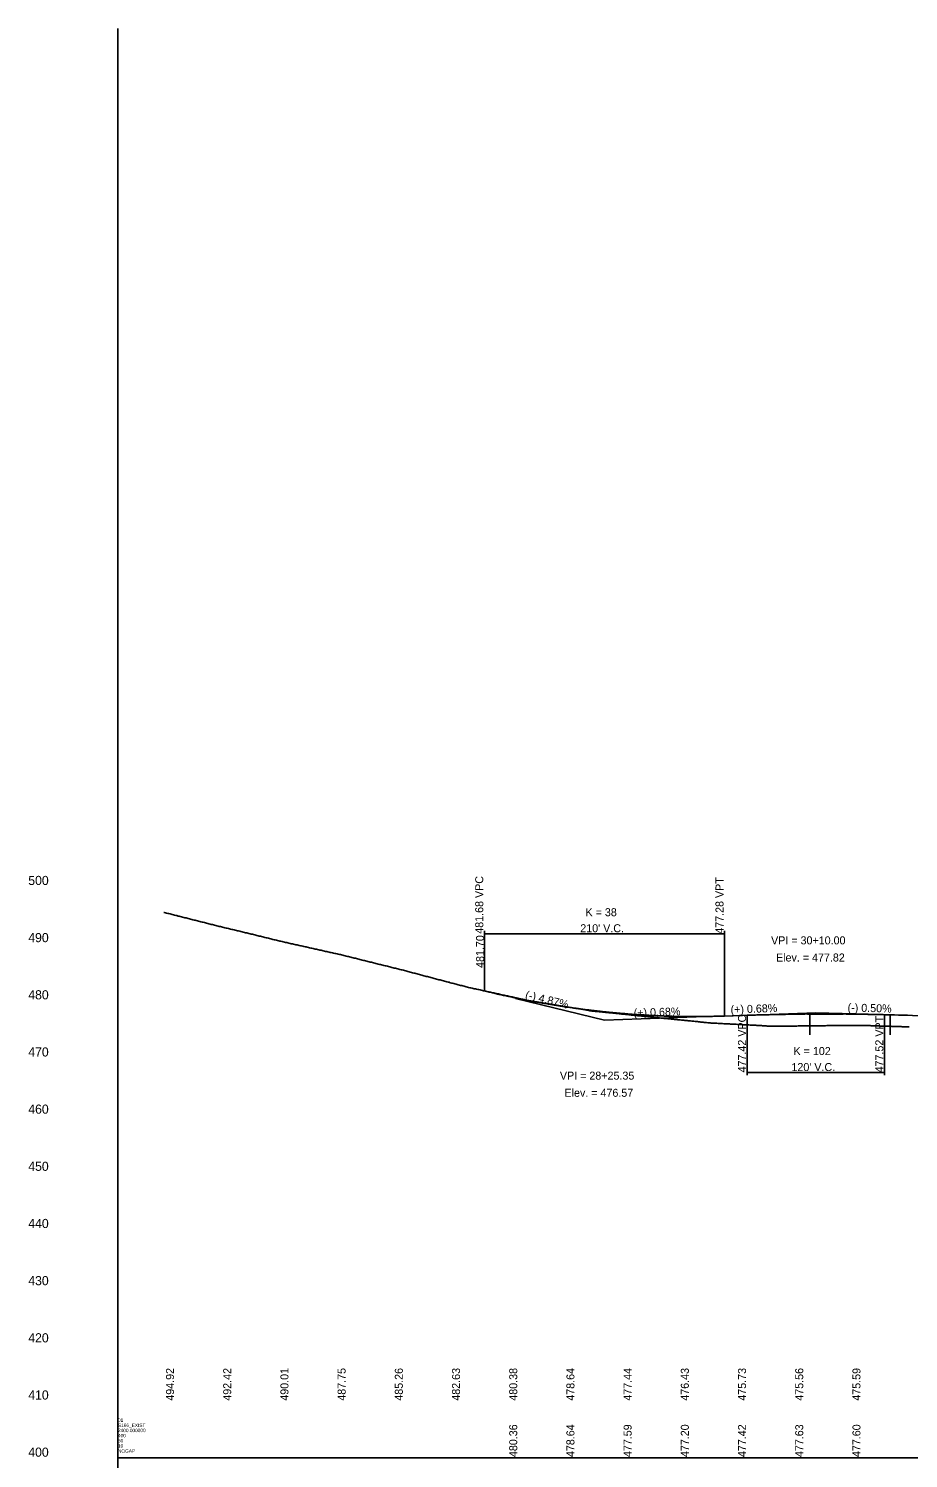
# Model space of a CAD drawing. Extents: x 1690070 to 1696783, y 823417 to 829859.
# Drawn here: x 1695305 to 1696074, y 824666 to 825917 of the extents above; entities that cross this region are included whole.
import ezdxf

# ---------------------------------------------------------------- set-up
doc = ezdxf.new("R2010")
doc.units = 0
for name, color, linetype in [('RD_DDB_ElevTX', 7, 'Continuous'), ('RD_DDB_GradeTX', 7, 'Continuous'), ('RD_DDB_Profile_EX', 7, 'Continuous'), ('RD_DDB_Profile_Lbl', 7, 'Continuous'), ('RD_DDB_Profile_PR', 7, 'Continuous'), ('RD_DDB_StripGrade', 7, 'Continuous'), ('RD_DDB_VCLbl', 7, 'Continuous'), ('RD_GPK_Profile_Cell', 7, 'Continuous'), ('RD_PD_Bridge', 7, 'Continuous')]:
    doc.layers.add(name, color=color, linetype=linetype)

msp = doc.modelspace()

# ---------------------------------------------------------------- linework, layer by layer
at = {"layer": 'RD_DDB_GradeTX'}
for p, q in [((1695730.6, 825068.6), (1695808.3, 825049.6)), ((1695913, 825053.2), (1695993, 825055.9)), ((1696073, 825053.9), (1695993, 825055.9)), ((1695888.3, 825052.4), (1695808.3, 825049.6))]:
    msp.add_line(p, q, dxfattribs=at)
at = {"layer": 'RD_DDB_Profile_EX'}
for points in [[(1695423, 825143.9), (1695423.5, 825143.8), (1695424.5, 825143.5), (1695425.5, 825143.3), (1695426.5, 825143), (1695427.5, 825142.8), (1695428.5, 825142.5), (1695429.5, 825142.2), (1695430.5, 825142), (1695431.5, 825141.7), (1695432.5, 825141.5), (1695433.5, 825141.2), (1695434.5, 825141), (1695435.5, 825140.7), (1695436.5, 825140.5), (1695437.5, 825140.2), (1695438.5, 825140), (1695439.5, 825139.7), (1695440.5, 825139.5), (1695441.5, 825139.2), (1695442.5, 825139), (1695443.5, 825138.7), (1695444.5, 825138.5), (1695445.5, 825138.2), (1695446.5, 825138), (1695447.5, 825137.7), (1695448.5, 825137.5), (1695449.5, 825137.2), (1695450.5, 825137), (1695451.5, 825136.7), (1695452.5, 825136.5), (1695453.5, 825136.2), (1695454.5, 825135.9), (1695455.5, 825135.7), (1695456.5, 825135.4), (1695457.5, 825135.2), (1695458.5, 825134.9), (1695459.5, 825134.7), (1695460.5, 825134.4), (1695461.5, 825134.2), (1695462.5, 825133.9), (1695463.5, 825133.7), (1695464.5, 825133.4), (1695465.5, 825133.2), (1695466.5, 825132.9), (1695467.5, 825132.7), (1695468.5, 825132.4), (1695469.5, 825132.1), (1695470.5, 825131.9), (1695471.5, 825131.6), (1695472.5, 825131.4), (1695473.5, 825131.2), (1695474.5, 825130.9), (1695475.5, 825130.7), (1695476.5, 825130.4), (1695477.5, 825130.2), (1695478.5, 825130), (1695479.5, 825129.7), (1695480.5, 825129.5), (1695481.5, 825129.2), (1695482.5, 825129), (1695483.5, 825128.8), (1695484.5, 825128.5), (1695485.5, 825128.3), (1695486.5, 825128), (1695487.5, 825127.8), (1695488.5, 825127.6), (1695489.5, 825127.3), (1695490.5, 825127.1), (1695491.5, 825126.8), (1695492.5, 825126.6), (1695493.5, 825126.3), (1695494.5, 825126.1), (1695495.5, 825125.9), (1695496.5, 825125.6), (1695497.5, 825125.4), (1695498.5, 825125.1), (1695499.5, 825124.9), (1695500.5, 825124.7), (1695501.5, 825124.4), (1695502.5, 825124.2), (1695503.5, 825123.9), (1695504.5, 825123.7), (1695505.5, 825123.4), (1695506.5, 825123.2), (1695507.5, 825123), (1695508.5, 825122.7), (1695509.5, 825122.5), (1695510.5, 825122.2), (1695511.5, 825122), (1695512.5, 825121.7), (1695513.5, 825121.5), (1695514.5, 825121.3), (1695515.5, 825121), (1695516.5, 825120.8), (1695517.5, 825120.5), (1695518.5, 825120.3), (1695519.5, 825120), (1695520.5, 825119.8), (1695521.5, 825119.6), (1695522.5, 825119.3)], [(1695522.5, 825119.3), (1695523.5, 825119.1), (1695524.5, 825118.8), (1695525.5, 825118.6), (1695526.5, 825118.3), (1695527.5, 825118.1), (1695528.5, 825117.8), (1695529.5, 825117.6), (1695530.5, 825117.4), (1695531.5, 825117.2), (1695532.5, 825117), (1695533.5, 825116.7), (1695534.5, 825116.5), (1695535.5, 825116.3), (1695536.5, 825116.1), (1695537.5, 825115.8), (1695538.5, 825115.6), (1695539.5, 825115.4), (1695540.5, 825115.2), (1695541.5, 825114.9), (1695542.5, 825114.7), (1695543.5, 825114.5), (1695544.5, 825114.3), (1695545.5, 825114), (1695546.5, 825113.8), (1695547.5, 825113.6), (1695548.5, 825113.4), (1695549.5, 825113.1), (1695550.5, 825112.9), (1695551.5, 825112.7), (1695552.5, 825112.5), (1695553.5, 825112.2), (1695554.5, 825112), (1695555.5, 825111.8), (1695556.5, 825111.6), (1695557.5, 825111.3), (1695558.5, 825111.1), (1695559.5, 825110.9), (1695560.5, 825110.7), (1695561.5, 825110.5), (1695562.5, 825110.2), (1695563.5, 825110), (1695564.5, 825109.8), (1695565.5, 825109.6), (1695566.5, 825109.3), (1695567.5, 825109.1), (1695568.5, 825108.9), (1695569.5, 825108.7), (1695570.5, 825108.4), (1695571.5, 825108.2), (1695572.5, 825108), (1695573.5, 825107.8), (1695574.5, 825107.5), (1695575.5, 825107.3), (1695576.5, 825107.1), (1695577.5, 825106.9), (1695578.5, 825106.6), (1695579.5, 825106.4), (1695580.5, 825106.2), (1695581.5, 825105.9), (1695582.5, 825105.6), (1695583.5, 825105.4), (1695584.5, 825105.2), (1695585.5, 825104.9), (1695586.5, 825104.7), (1695587.5, 825104.4), (1695588.5, 825104.2), (1695589.5, 825103.9), (1695590.5, 825103.7), (1695591.5, 825103.4), (1695592.5, 825103.2), (1695593.5, 825102.9), (1695594.5, 825102.7), (1695595.5, 825102.4), (1695596.5, 825102.2), (1695597.5, 825101.9), (1695598.5, 825101.7), (1695599.5, 825101.4), (1695600.5, 825101.2), (1695601.5, 825100.9), (1695602.5, 825100.7), (1695603.5, 825100.4), (1695604.5, 825100.2), (1695605.5, 825099.9), (1695606.5, 825099.7), (1695607.5, 825099.4), (1695608.5, 825099.2), (1695609.5, 825098.9), (1695610.5, 825098.7), (1695611.5, 825098.4), (1695612.5, 825098.2), (1695613.5, 825097.9), (1695614.5, 825097.7), (1695615.5, 825097.5), (1695616.5, 825097.2), (1695617.5, 825097), (1695618.5, 825096.7), (1695619.5, 825096.5), (1695620.5, 825096.2), (1695621.5, 825096), (1695622.5, 825095.7)], [(1695622.5, 825095.7), (1695623.5, 825095.5), (1695624.5, 825095.2), (1695625.5, 825095), (1695626.5, 825094.7), (1695627.5, 825094.5), (1695628.5, 825094.2), (1695629.5, 825094), (1695630.5, 825093.7), (1695631.5, 825093.5), (1695632.5, 825093.2), (1695633.5, 825093), (1695634.5, 825092.7), (1695635.5, 825092.4), (1695636.5, 825092.2), (1695637.5, 825091.9), (1695638.5, 825091.6), (1695639.5, 825091.4), (1695640.5, 825091.1), (1695641.5, 825090.8), (1695642.5, 825090.6), (1695643.5, 825090.3), (1695644.5, 825090.1), (1695645.5, 825089.8), (1695646.5, 825089.5), (1695647.5, 825089.3), (1695648.5, 825089), (1695649.5, 825088.7), (1695650.5, 825088.5), (1695651.5, 825088.2), (1695652.5, 825087.9), (1695653.5, 825087.7), (1695654.5, 825087.4), (1695655.5, 825087.2), (1695656.5, 825086.9), (1695657.5, 825086.6), (1695658.5, 825086.4), (1695659.5, 825086.1), (1695660.5, 825085.8), (1695661.5, 825085.6), (1695662.5, 825085.3), (1695663.5, 825085), (1695664.5, 825084.8), (1695665.5, 825084.5), (1695666.5, 825084.3), (1695667.5, 825084), (1695668.5, 825083.7), (1695669.5, 825083.5), (1695670.5, 825083.2), (1695671.5, 825082.9), (1695672.5, 825082.7), (1695673.5, 825082.4), (1695674.5, 825082.1), (1695675.5, 825081.9), (1695676.5, 825081.6), (1695677.5, 825081.4), (1695678.5, 825081.1), (1695679.5, 825080.8), (1695680.5, 825080.6), (1695681.5, 825080.3), (1695682.5, 825080), (1695683.5, 825079.8), (1695684.5, 825079.5), (1695685.5, 825079.2), (1695686.5, 825079), (1695687.5, 825078.7), (1695688.5, 825078.5), (1695689.5, 825078.2), (1695690.5, 825078), (1695691.5, 825077.8), (1695692.5, 825077.6), (1695693.5, 825077.4), (1695694.5, 825077.1), (1695695.5, 825076.9), (1695696.5, 825076.7), (1695697.5, 825076.5), (1695698.5, 825076.3), (1695699.5, 825076), (1695700.5, 825075.8), (1695701.5, 825075.6), (1695702.5, 825075.4), (1695703.5, 825075.2), (1695704.5, 825074.9), (1695705.5, 825074.7), (1695706.5, 825074.5), (1695707.5, 825074.3), (1695708.5, 825074.1), (1695709.5, 825073.8), (1695710.5, 825073.6), (1695711.5, 825073.4), (1695712.5, 825073.2), (1695713.5, 825073), (1695714.5, 825072.7), (1695715.5, 825072.5), (1695716.5, 825072.3), (1695717.5, 825072.1), (1695718.5, 825071.9), (1695719.5, 825071.6), (1695720.5, 825071.4), (1695721.5, 825071.2), (1695722.5, 825071)], [(1695722.5, 825071), (1695723.5, 825070.8), (1695724.5, 825070.5), (1695725.5, 825070.3), (1695726.5, 825070.1), (1695727.5, 825069.9), (1695728.5, 825069.7), (1695729.5, 825069.4), (1695730.5, 825069.2), (1695731.5, 825069), (1695732.5, 825068.8), (1695733.5, 825068.6), (1695734.5, 825068.3), (1695735.5, 825068.1), (1695736.5, 825067.9), (1695737.5, 825067.7), (1695738.5, 825067.5), (1695739.5, 825067.2), (1695740.5, 825067), (1695741.5, 825066.8), (1695742.5, 825066.6), (1695743.5, 825066.5), (1695744.5, 825066.3), (1695745.5, 825066.1), (1695746.5, 825066), (1695747.5, 825065.8), (1695748.5, 825065.6), (1695749.5, 825065.5), (1695750.5, 825065.3), (1695751.5, 825065.2), (1695752.5, 825065), (1695753.5, 825064.8), (1695754.5, 825064.7), (1695755.5, 825064.5), (1695756.5, 825064.3), (1695757.5, 825064.2), (1695758.5, 825064), (1695759.5, 825063.8), (1695760.5, 825063.7), (1695761.5, 825063.5), (1695762.5, 825063.4), (1695763.5, 825063.2), (1695764.5, 825063), (1695765.5, 825062.9), (1695766.5, 825062.7), (1695767.5, 825062.5), (1695768.5, 825062.4), (1695769.5, 825062.2), (1695770.5, 825062), (1695771.5, 825061.9), (1695772.5, 825061.7), (1695773.5, 825061.6), (1695774.5, 825061.4), (1695775.5, 825061.2), (1695776.5, 825061.1), (1695777.5, 825060.9), (1695778.5, 825060.7), (1695779.5, 825060.6), (1695780.5, 825060.4), (1695781.5, 825060.2), (1695782.5, 825060.1), (1695783.5, 825059.9), (1695784.5, 825059.7), (1695785.5, 825059.6), (1695786.5, 825059.4), (1695787.5, 825059.3), (1695788.5, 825059.1), (1695789.5, 825058.9), (1695790.5, 825058.8), (1695791.5, 825058.6), (1695792.5, 825058.4), (1695793.5, 825058.3), (1695794.5, 825058.1), (1695795.5, 825057.9), (1695796.5, 825057.8), (1695797.5, 825057.6), (1695798.5, 825057.5), (1695799.5, 825057.4), (1695800.5, 825057.3), (1695801.5, 825057.2), (1695802.5, 825057.1), (1695803.5, 825057), (1695804.5, 825056.9), (1695805.5, 825056.8), (1695806.5, 825056.7), (1695807.5, 825056.6), (1695808.5, 825056.5), (1695809.5, 825056.4), (1695810.5, 825056.3), (1695811.5, 825056.2), (1695812.5, 825056.1), (1695813.5, 825056), (1695814.5, 825055.9), (1695815.5, 825055.8), (1695816.5, 825055.7), (1695817.5, 825055.6), (1695818.5, 825055.5), (1695819.5, 825055.4), (1695820.5, 825055.3), (1695821.5, 825055.2), (1695822.5, 825055.1)], [(1695822.5, 825055.1), (1695823.5, 825055), (1695824.5, 825054.9), (1695825.5, 825054.8), (1695826.5, 825054.7), (1695827.5, 825054.6), (1695828.5, 825054.5), (1695829.5, 825054.4), (1695830.5, 825054.3), (1695831.5, 825054.1), (1695832.5, 825054), (1695833.5, 825053.9), (1695834.5, 825053.8), (1695835.5, 825053.7), (1695836.5, 825053.6), (1695837.5, 825053.5), (1695838.5, 825053.4), (1695839.5, 825053.3), (1695840.5, 825053.2), (1695841.5, 825053.1), (1695842.5, 825053), (1695843.5, 825052.9), (1695844.5, 825052.8), (1695845.5, 825052.7), (1695846.5, 825052.6), (1695847.5, 825052.5), (1695848.5, 825052.4), (1695849.5, 825052.3), (1695850.5, 825052.2), (1695851.5, 825052.1), (1695852.5, 825052), (1695853.5, 825051.9), (1695854.5, 825051.8), (1695855.5, 825051.7), (1695856.5, 825051.6), (1695857.5, 825051.5), (1695858.5, 825051.4), (1695859.5, 825051.3), (1695860.5, 825051.2), (1695861.5, 825051.1), (1695862.5, 825051), (1695863.5, 825050.9), (1695864.5, 825050.8), (1695865.5, 825050.7), (1695866.5, 825050.6), (1695867.5, 825050.5), (1695868.5, 825050.4), (1695869.5, 825050.3), (1695870.5, 825050.2), (1695871.5, 825050.1), (1695872.5, 825050), (1695873.5, 825049.9), (1695874.5, 825049.8), (1695875.5, 825049.7), (1695876.5, 825049.6), (1695877.5, 825049.5), (1695878.5, 825049.4), (1695879.5, 825049.3), (1695880.5, 825049.2), (1695881.5, 825049.1), (1695882.5, 825049), (1695883.5, 825048.9), (1695884.5, 825048.8), (1695885.5, 825048.7), (1695886.5, 825048.6), (1695887.5, 825048.5), (1695888.5, 825048.4), (1695889.5, 825048.3), (1695890.5, 825048.2), (1695891.5, 825048.1), (1695892.5, 825048), (1695893.5, 825047.9), (1695894.5, 825047.8), (1695895.5, 825047.7), (1695896.5, 825047.6), (1695897.5, 825047.5), (1695898.5, 825047.4), (1695899.5, 825047.3), (1695900.5, 825047.2), (1695901.5, 825047.1), (1695902.5, 825047.1), (1695903.5, 825047), (1695904.5, 825047), (1695905.5, 825046.9), (1695906.5, 825046.9), (1695907.5, 825046.8), (1695908.5, 825046.8), (1695909.5, 825046.7), (1695910.5, 825046.7), (1695911.5, 825046.6), (1695912.5, 825046.5), (1695913.5, 825046.5), (1695914.5, 825046.4), (1695915.5, 825046.4), (1695916.5, 825046.3), (1695917.5, 825046.3), (1695918.5, 825046.2), (1695919.5, 825046.2), (1695920.5, 825046.1), (1695921.5, 825046.1), (1695922.5, 825046)], [(1695922.5, 825046), (1695923.5, 825046), (1695924.5, 825045.9), (1695925.5, 825045.9), (1695926.5, 825045.8), (1695927.5, 825045.7), (1695928.5, 825045.7), (1695929.5, 825045.6), (1695930.5, 825045.6), (1695931.5, 825045.5), (1695932.5, 825045.5), (1695933.5, 825045.4), (1695934.5, 825045.4), (1695935.5, 825045.3), (1695936.5, 825045.3), (1695937.5, 825045.2), (1695938.5, 825045.2), (1695939.5, 825045.1), (1695940.5, 825045.1), (1695941.5, 825045), (1695942.5, 825044.9), (1695943.5, 825044.9), (1695944.5, 825044.8), (1695945.5, 825044.8), (1695946.5, 825044.7), (1695947.5, 825044.7), (1695948.5, 825044.6), (1695949.5, 825044.6), (1695950.5, 825044.5), (1695951.5, 825044.5), (1695952.5, 825044.4), (1695953.5, 825044.4), (1695954.5, 825044.4), (1695955.5, 825044.4), (1695956.5, 825044.4), (1695957.5, 825044.4), (1695958.5, 825044.4), (1695959.5, 825044.4), (1695960.5, 825044.4), (1695961.5, 825044.4), (1695962.5, 825044.4), (1695963.5, 825044.4), (1695964.5, 825044.5), (1695965.5, 825044.5), (1695966.5, 825044.5), (1695967.5, 825044.5), (1695968.5, 825044.5), (1695969.5, 825044.5), (1695970.5, 825044.5), (1695971.5, 825044.5), (1695972.5, 825044.5), (1695973.5, 825044.5), (1695974.5, 825044.5), (1695975.5, 825044.5), (1695976.5, 825044.5), (1695977.5, 825044.6), (1695978.5, 825044.6), (1695979.5, 825044.6), (1695980.5, 825044.6), (1695981.5, 825044.6), (1695982.5, 825044.6), (1695983.5, 825044.6), (1695984.5, 825044.6), (1695985.5, 825044.6), (1695986.5, 825044.6), (1695987.5, 825044.6), (1695988.5, 825044.6), (1695989.5, 825044.6), (1695990.5, 825044.7), (1695991.5, 825044.7), (1695992.5, 825044.7), (1695993.5, 825044.7), (1695994.5, 825044.7), (1695995.5, 825044.7), (1695996.5, 825044.7), (1695997.5, 825044.7), (1695998.5, 825044.7), (1695999.5, 825044.7), (1696000.5, 825044.7), (1696001.5, 825044.7), (1696002.5, 825044.8), (1696003.5, 825044.8), (1696004.5, 825044.8), (1696005.5, 825044.8), (1696006.5, 825044.8), (1696007.5, 825044.8), (1696008.5, 825044.8), (1696009.5, 825044.8), (1696010.5, 825044.8), (1696011.5, 825044.8), (1696012.5, 825044.8), (1696013.5, 825044.8), (1696014.5, 825044.8), (1696015.5, 825044.8), (1696016.5, 825044.8), (1696017.5, 825044.8), (1696018.5, 825044.8), (1696019.5, 825044.8), (1696020.5, 825044.8), (1696021.5, 825044.8), (1696022.5, 825044.8)], [(1696022.5, 825044.8), (1696023.5, 825044.8), (1696024.5, 825044.8), (1696025.5, 825044.8), (1696026.5, 825044.8), (1696027.5, 825044.8), (1696028.5, 825044.8), (1696029.5, 825044.8), (1696030.5, 825044.8), (1696031.5, 825044.8), (1696032.5, 825044.8), (1696033.5, 825044.8), (1696034.5, 825044.8), (1696035.5, 825044.8), (1696036.5, 825044.8), (1696037.5, 825044.8), (1696038.5, 825044.8), (1696039.5, 825044.8), (1696040.5, 825044.8), (1696041.5, 825044.7), (1696042.5, 825044.7), (1696043.5, 825044.7), (1696044.5, 825044.7), (1696045.5, 825044.7), (1696046.5, 825044.6), (1696047.5, 825044.6), (1696048.5, 825044.6), (1696049.5, 825044.5), (1696050.5, 825044.5), (1696051.5, 825044.5), (1696052.5, 825044.4), (1696053.5, 825044.4), (1696054.5, 825044.4), (1696055.5, 825044.4), (1696056.5, 825044.3), (1696057.5, 825044.3), (1696058.5, 825044.3), (1696059.5, 825044.2), (1696060.5, 825044.2), (1696061.5, 825044.2), (1696062.5, 825044.1), (1696063.5, 825044.1), (1696064.5, 825044.1), (1696065.5, 825044), (1696066.5, 825044), (1696067.5, 825044), (1696068.5, 825043.9), (1696069.5, 825043.9), (1696070.5, 825043.9), (1696071.5, 825043.8), (1696072.5, 825043.8), (1696073.5, 825043.8), (1696074.5, 825043.8)]]:
    msp.add_lwpolyline(points, dxfattribs=at)
at = {"layer": 'RD_DDB_Profile_PR'}
for p, q in [((1695703, 825075.3), (1695703.3, 825075.2)), ((1695913.3, 825053.2), (1695933, 825053.9)), ((1696053, 825054.4), (1696156.7, 825051.8))]:
    msp.add_line(p, q, dxfattribs=at)
for points in [[(1695703.3, 825075.2), (1695707.5, 825074.2), (1695711.7, 825073.2), (1695715.9, 825072.2), (1695720.1, 825071.3), (1695724.3, 825070.4), (1695728.5, 825069.5), (1695732.7, 825068.6), (1695736.9, 825067.8), (1695741.1, 825066.9), (1695745.3, 825066.1), (1695749.5, 825065.4), (1695753.7, 825064.6), (1695757.9, 825063.9), (1695762.1, 825063.2), (1695766.3, 825062.5), (1695770.5, 825061.8), (1695774.7, 825061.2), (1695778.9, 825060.6), (1695783.1, 825060), (1695787.3, 825059.4), (1695791.5, 825058.9), (1695795.7, 825058.4), (1695799.9, 825057.9), (1695804.1, 825057.4), (1695808.3, 825056.9), (1695812.5, 825056.5), (1695816.7, 825056.1), (1695820.9, 825055.7), (1695825.1, 825055.4), (1695829.3, 825055), (1695833.5, 825054.7), (1695837.7, 825054.4), (1695841.9, 825054.2), (1695846.1, 825053.9), (1695850.3, 825053.7), (1695854.5, 825053.5), (1695858.7, 825053.3), (1695862.9, 825053.2), (1695867.1, 825053), (1695871.3, 825052.9), (1695875.5, 825052.9), (1695879.7, 825052.8), (1695883.9, 825052.8), (1695888.1, 825052.8), (1695892.3, 825052.8), (1695896.5, 825052.8), (1695900.7, 825052.9), (1695904.9, 825053), (1695909.1, 825053.1), (1695913.3, 825053.2)], [(1695933, 825053.9), (1695935.4, 825053.9), (1695937.8, 825054), (1695940.2, 825054.1), (1695942.6, 825054.2), (1695945, 825054.2), (1695947.4, 825054.3), (1695949.8, 825054.4), (1695952.2, 825054.4), (1695954.6, 825054.5), (1695957, 825054.5), (1695959.4, 825054.6), (1695961.8, 825054.6), (1695964.2, 825054.7), (1695966.6, 825054.7), (1695969, 825054.8), (1695971.4, 825054.8), (1695973.8, 825054.8), (1695976.2, 825054.9), (1695978.6, 825054.9), (1695981, 825054.9), (1695983.4, 825055), (1695985.8, 825055), (1695988.2, 825055), (1695990.6, 825055), (1695993, 825055), (1695995.4, 825055), (1695997.8, 825055), (1696000.2, 825055), (1696002.6, 825055), (1696005, 825055), (1696007.4, 825055), (1696009.8, 825055), (1696012.2, 825055), (1696014.6, 825055), (1696017, 825055), (1696019.4, 825055), (1696021.8, 825054.9), (1696024.2, 825054.9), (1696026.6, 825054.9), (1696029, 825054.9), (1696031.4, 825054.8), (1696033.8, 825054.8), (1696036.2, 825054.8), (1696038.6, 825054.7), (1696041, 825054.7), (1696043.4, 825054.6), (1696045.8, 825054.6), (1696048.2, 825054.5), (1696050.6, 825054.5), (1696053, 825054.4)]]:
    msp.add_spline(points, degree=3, dxfattribs=at)
at = {"layer": 'RD_DDB_VCLbl'}
for p, q in [((1695703.3, 825127.7), (1695703.3, 825075.2)), ((1695703.3, 825125.2), (1695913.3, 825125.2)), ((1695913.3, 825127.7), (1695913.3, 825053.2)), ((1695933, 825001.4), (1695933, 825053.9)), ((1696053, 825001.4), (1696053, 825054.4)), ((1695933, 825003.9), (1696053, 825003.9))]:
    msp.add_line(p, q, dxfattribs=at)
at = {"layer": 'RD_GPK_Profile_Cell'}
for q in [(1695383, 825916.8), (1696783, 824666.8), (1695383, 823416.8)]:
    msp.add_line((1695383, 824666.8), q, dxfattribs=at)
at = {"layer": 'RD_PD_Bridge'}
for p, q in [((1695987.9, 825036.8), (1695987.9, 825054.6)), ((1696057.9, 825036.8), (1696057.9, 825054.3))]:
    msp.add_line(p, q, dxfattribs=at)

# ---------------------------------------------------------------- texts
at = {"layer": 'RD_DDB_ElevTX'}
for s, p in [('500', (1695304.6, 825167.8)), ('490', (1695304.6, 825117.8)), ('480', (1695304.6, 825067.8)), ('470', (1695304.6, 825017.8)), ('460', (1695304.6, 824967.8)), ('450', (1695304.6, 824917.8)), ('440', (1695304.6, 824867.8)), ('430', (1695304.6, 824817.8)), ('420', (1695304.6, 824767.8)), ('410', (1695304.6, 824717.8)), ('400', (1695304.6, 824667.8))]:
    msp.add_text(s, height=8, dxfattribs=at).set_placement(p)
at = {"layer": 'RD_DDB_GradeTX'}
for s, rotation, p in [('(-) 4.87%', 346.3199, (1695738.5, 825068.7)), ('(+) 0.68%', 1.9391, (1695833.9, 825052.5)), ('(+) 0.68%', 1.9391, (1695918.6, 825055.4)), ('(-) 0.50%', 358.5679, (1696020.7, 825057.2))]:
    msp.add_text(s, height=7, rotation=rotation, dxfattribs=at).set_placement(p)
at = {"layer": 'RD_DDB_Profile_Lbl'}
msp.add_text('481.70', height=7, rotation=90, dxfattribs=at).set_placement((1695703, 825095.3))
for s, p in [('VPI = 30+10.00', (1695953.9, 825115.9)), ('Elev. = 477.82', (1695958.2, 825100.9)), ('VPI = 28+25.35', (1695769.3, 824997.6)), ('Elev. = 476.57', (1695773.3, 824982.6))]:
    msp.add_text(s, height=7, dxfattribs=at).set_placement(p)
at = {"layer": 'RD_DDB_StripGrade'}
for s, p in [('481.68 VPC', (1695702.3, 825125.2)), ('477.28 VPT', (1695912.3, 825125.2)), ('477.42 VPC', (1695932, 825003.9)), ('477.52 VPT', (1696052, 825003.9)), ('494.92', (1695432, 824716.8)), ('492.42', (1695482, 824716.8)), ('490.01', (1695532, 824716.8)), ('487.75', (1695582, 824716.8)), ('485.26', (1695632, 824716.8)), ('482.63', (1695682, 824716.8)), ('480.38', (1695732, 824716.8)), ('478.64', (1695782, 824716.8)), ('477.44', (1695832, 824716.8)), ('476.43', (1695882, 824716.8)), ('475.73', (1695932, 824716.8)), ('475.56', (1695982, 824716.8)), ('475.59', (1696032, 824716.8)), ('480.36', (1695732, 824667.5)), ('478.64', (1695782, 824667.5)), ('477.59', (1695832, 824667.5)), ('477.20', (1695882, 824667.5)), ('477.42', (1695932, 824667.5)), ('477.63', (1695982, 824667.5)), ('477.60', (1696032, 824667.5))]:
    msp.add_text(s, height=7, rotation=90, dxfattribs=at).set_placement(p)
at = {"layer": 'RD_DDB_VCLbl'}
for s, p in [('K = 38', (1695791.7, 825140.5)), ("210' V.C.", (1695787.1, 825126.5)), ('K = 102', (1695973.5, 825019.1)), ("120' V.C.", (1695971.7, 825005.1))]:
    msp.add_text(s, height=7, dxfattribs=at).set_placement(p)
at = {"layer": 'RD_GPK_Profile_Cell'}
for s, p in [('01', (1695383, 824698.3)), ('S166_EXIST', (1695383, 824693.8)), ('2400.000000', (1695383, 824689.3)), ('400', (1695383, 824684.8)), ('50', (1695383, 824680.3)), ('10', (1695383, 824675.8)), ('NOGAP', (1695383, 824671.3))]:
    msp.add_text(s, height=3, dxfattribs=at).set_placement(p)

doc.saveas('drawing.dxf')
